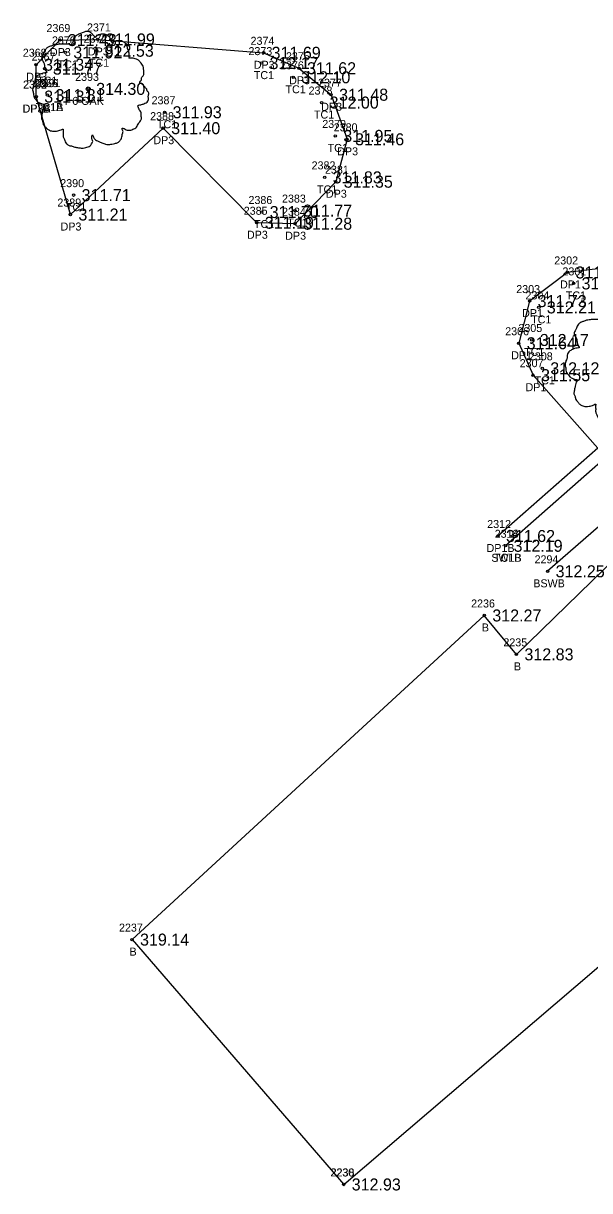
# Model space of a CAD drawing. Extents: x 1970076 to 1971136, y 803126 to 804215.
# Drawn here: x 1970276.2 to 1970347, y 803647.9 to 803793.8 of the extents above; entities that cross this region are included whole.
import ezdxf

# ---------------------------------------------------------------- set-up
doc = ezdxf.new("R2010")
doc.units = 0
for name, color, linetype in [('RD_EX_Bldg', 7, 'Continuous'), ('RD_EX_Bldg_txCode', 7, 'Continuous'), ('RD_EX_Conc', 7, 'Continuous'), ('RD_EX_Conc_txCode', 7, 'Continuous'), ('RD_EX_Driveway', 7, 'Continuous'), ('RD_EX_Driveway_txCode', 7, 'Continuous'), ('RD_EX_TX_Bldg_ELEV', 7, 'Continuous'), ('RD_EX_TX_Conc_ELEV', 7, 'Continuous'), ('RD_EX_TX_Driveway_ELEV', 7, 'Continuous'), ('RD_EX_TX_VEG_ELEV', 7, 'Continuous'), ('RD_EX_VEG', 7, 'Continuous'), ('RD_EX_VEG_txCode', 7, 'Continuous'), ('RD_SMD_Locator', 7, 'Continuous')]:
    doc.layers.add(name, color=color, linetype=linetype)

msp = doc.modelspace()

# ---------------------------------------------------------------- linework, layer by layer
at = {"layer": 'RD_EX_Bldg'}
msp.add_lwpolyline([(1970316.24, 803648.65), (1970363.89, 803689.38), (1970360.37, 803693.37), (1970387.33, 803715.2), (1970364.46, 803740.81), (1970337.82, 803714.9), (1970333.81, 803719.76), (1970289.79, 803679.25), (1970316.24, 803648.65)], dxfattribs=at)
at = {"layer": 'RD_EX_Conc'}
for points in [[(1970388.04, 803714.57), (1970387.81, 803720.9), (1970384.41, 803726.13), (1970362.2, 803751.39), (1970350.07, 803740.46), (1970336.46, 803728.47)], [(1970388.04, 803714.57), (1970384.87, 803718.14), (1970385.63, 803718.83), (1970368.14, 803738.61), (1970367.29, 803737.93), (1970364.41, 803741.02), (1970364.34, 803740.94), (1970361.22, 803738.42), (1970359.25, 803740.53), (1970341.72, 803725.28)]]:
    msp.add_lwpolyline(points, dxfattribs=at)
at = {"layer": 'RD_EX_Driveway'}
for points in [[(1970277.82, 803784.61), (1970277.79, 803788.59), (1970280.75, 803791.67), (1970285.5, 803791.75), (1970306.23, 803790.08), (1970310.65, 803788.15), (1970314.66, 803784.84), (1970316.66, 803779.27), (1970315.24, 803773.97), (1970310.16, 803768.72), (1970305.38, 803768.84), (1970293.68, 803780.66), (1970282.09, 803769.87), (1970277.82, 803784.61)], [(1970361.58, 803685.25), (1970385.16, 803706.07), (1970389.47, 803713.84), (1970389.3, 803721.4), (1970385.52, 803727.12), (1970356.23, 803760.4), (1970349.72, 803763.3), (1970344.21, 803762.63), (1970339.47, 803759.05), (1970338.11, 803753.78), (1970339.9, 803749.79), (1970347.99, 803740.68), (1970335.51, 803729.69)]]:
    msp.add_lwpolyline(points, dxfattribs=at)
at = {"layer": 'RD_EX_VEG'}
for centre, radius in [((1970284.31, 803785.57), 0.25), ((1970284.3, 803785.55), 0.0001)]:
    msp.add_circle(centre, radius, dxfattribs=at)
for points in [[(1970284.45, 803792.74), (1970284.15, 803792.76), (1970283.82, 803792.66), (1970283.57, 803792.56), (1970283.35, 803792.49), (1970283.12, 803792.39), (1970282.82, 803792.22), (1970282.6, 803792.02), (1970282.47, 803791.77), (1970282.42, 803791.54), (1970282.37, 803791.27), (1970282.37, 803791.09), (1970282.25, 803791.07), (1970282.1, 803791.09), (1970281.85, 803791.17), (1970281.6, 803791.17), (1970281.35, 803791.17), (1970281, 803791.14), (1970280.65, 803791.14), (1970280.37, 803791.09), (1970280.05, 803791.04), (1970279.67, 803790.92), (1970279.32, 803790.79), (1970279.02, 803790.54), (1970278.77, 803790.07), (1970278.65, 803789.72), (1970278.5, 803789.47), (1970278.65, 803789.02), (1970278.82, 803788.67), (1970278.85, 803788.47), (1970278.92, 803788.04), (1970279.02, 803787.82), (1970279.15, 803787.62), (1970279.07, 803787.59), (1970278.7, 803787.54), (1970278.4, 803787.44), (1970277.97, 803787.22), (1970277.75, 803786.99), (1970277.65, 803786.67), (1970277.62, 803786.32), (1970277.52, 803786.12), (1970277.45, 803785.84), (1970277.42, 803785.77), (1970277.37, 803785.44), (1970277.47, 803784.99), (1970277.5, 803784.64), (1970277.62, 803784.42), (1970277.77, 803784.24), (1970277.95, 803783.99), (1970278.35, 803783.77), (1970278.67, 803783.67), (1970278.87, 803783.64), (1970278.7, 803783.14), (1970278.65, 803782.79), (1970278.52, 803782.39), (1970278.52, 803782.32), (1970278.47, 803781.84), (1970278.62, 803781.52), (1970278.7, 803781.14), (1970278.87, 803780.92), (1970279.15, 803780.62), (1970279.47, 803780.4), (1970279.97, 803780.27), (1970280.37, 803780.3), (1970280.95, 803780.47), (1970281.2, 803780.55), (1970281.17, 803780.37), (1970281.2, 803780), (1970281.2, 803779.57), (1970281.35, 803779.25), (1970281.45, 803778.97), (1970281.6, 803778.72), (1970281.92, 803778.5), (1970282.32, 803778.42), (1970282.75, 803778.27), (1970283.2, 803778.2), (1970283.7, 803778.17), (1970284.3, 803778.32), (1970284.57, 803778.45), (1970284.67, 803778.62), (1970284.87, 803779), (1970284.82, 803779.22), (1970284.84, 803779.82), (1970284.94, 803779.65), (1970285.12, 803779.3), (1970285.62, 803779), (1970286.02, 803778.82), (1970286.49, 803778.67), (1970286.79, 803778.6), (1970287.27, 803778.67), (1970287.64, 803778.75), (1970288.02, 803778.87), (1970288.32, 803779.15), (1970288.49, 803779.42), (1970288.54, 803779.7), (1970288.62, 803780.07), (1970288.67, 803780.25)], [(1970288.67, 803780.25), (1970288.59, 803780.42), (1970288.54, 803780.67), (1970288.62, 803780.65), (1970288.79, 803780.6), (1970289.07, 803780.47), (1970289.29, 803780.4), (1970289.62, 803780.42), (1970289.89, 803780.52), (1970290.34, 803780.8), (1970290.62, 803781.27), (1970290.89, 803781.67), (1970290.97, 803781.99), (1970290.92, 803782.22), (1970290.89, 803782.72), (1970290.69, 803782.97), (1970290.64, 803783.09), (1970290.54, 803783.49), (1970290.62, 803783.54), (1970290.89, 803783.59), (1970291.27, 803783.72), (1970291.54, 803783.84), (1970291.77, 803784.02), (1970291.84, 803784.24), (1970291.82, 803784.64), (1970291.87, 803785.04), (1970291.79, 803785.19), (1970291.69, 803785.34), (1970291.62, 803785.54), (1970291.47, 803785.69), (1970291.37, 803785.84), (1970291.27, 803785.94), (1970291.14, 803786.09), (1970290.97, 803786.22), (1970290.82, 803786.27), (1970290.77, 803786.42), (1970290.92, 803786.62), (1970290.97, 803786.72), (1970290.99, 803786.94), (1970291.22, 803787.29), (1970291.27, 803787.69), (1970291.22, 803788.12), (1970291.17, 803788.39), (1970291.02, 803788.67), (1970290.82, 803788.92), (1970290.69, 803789.09), (1970290.52, 803789.22), (1970290.19, 803789.34), (1970289.94, 803789.39), (1970289.59, 803789.39), (1970289.39, 803789.44), (1970289.42, 803789.49), (1970289.42, 803789.64), (1970289.42, 803789.92), (1970289.34, 803790.37), (1970289.19, 803790.87), (1970289.19, 803790.89), (1970289.09, 803791.14), (1970288.87, 803791.34), (1970288.69, 803791.44), (1970288.49, 803791.57), (1970288.24, 803791.59), (1970287.94, 803791.59), (1970287.67, 803791.54), (1970287.47, 803791.44), (1970287.29, 803791.32), (1970287.22, 803791.47), (1970287.12, 803791.77), (1970287.07, 803791.92), (1970286.92, 803792.09), (1970286.69, 803792.29), (1970286.24, 803792.41), (1970285.62, 803792.34), (1970285.32, 803792.14), (1970285.17, 803791.97), (1970285.12, 803792.09), (1970284.92, 803792.29), (1970284.82, 803792.46), (1970284.64, 803792.59), (1970284.5, 803792.69), (1970284.4, 803792.74)], [(1970350.98, 803758.35), (1970350.68, 803758.37), (1970350.35, 803758.27), (1970350.1, 803758.17), (1970349.88, 803758.1), (1970349.65, 803758), (1970349.35, 803757.82), (1970349.13, 803757.62), (1970349, 803757.37), (1970348.95, 803757.15), (1970348.9, 803756.87), (1970348.9, 803756.7), (1970348.78, 803756.67), (1970348.63, 803756.7), (1970348.38, 803756.77), (1970348.13, 803756.77), (1970347.88, 803756.77), (1970347.53, 803756.75), (1970347.18, 803756.75), (1970346.9, 803756.7), (1970346.58, 803756.65), (1970346.21, 803756.52), (1970345.86, 803756.4), (1970345.56, 803756.15), (1970345.31, 803755.67), (1970345.18, 803755.32), (1970345.03, 803755.07), (1970345.18, 803754.62), (1970345.36, 803754.27), (1970345.38, 803754.07), (1970345.46, 803753.65), (1970345.56, 803753.42), (1970345.68, 803753.22), (1970345.61, 803753.2), (1970345.23, 803753.15), (1970344.93, 803753.05), (1970344.51, 803752.82), (1970344.28, 803752.6), (1970344.18, 803752.27), (1970344.16, 803751.92), (1970344.06, 803751.72), (1970343.98, 803751.45), (1970343.96, 803751.37), (1970343.91, 803751.05), (1970344.01, 803750.6), (1970344.03, 803750.25), (1970344.16, 803750.02), (1970344.31, 803749.85), (1970344.48, 803749.6), (1970344.88, 803749.37), (1970345.21, 803749.27), (1970345.41, 803749.25), (1970345.23, 803748.75), (1970345.18, 803748.4), (1970345.06, 803748), (1970345.06, 803747.93), (1970345.01, 803747.45), (1970345.16, 803747.13), (1970345.23, 803746.75), (1970345.41, 803746.53), (1970345.68, 803746.23), (1970346.01, 803746), (1970346.51, 803745.88), (1970346.9, 803745.9), (1970347.48, 803746.08), (1970347.73, 803746.15), (1970347.7, 803745.98), (1970347.73, 803745.6), (1970347.73, 803745.18), (1970347.88, 803744.85), (1970347.98, 803744.58), (1970348.13, 803744.33), (1970348.45, 803744.1), (1970348.85, 803744.03), (1970349.28, 803743.88), (1970349.73, 803743.8), (1970350.23, 803743.78), (1970350.83, 803743.93), (1970351.1, 803744.05), (1970351.2, 803744.23), (1970351.4, 803744.6), (1970351.35, 803744.83), (1970351.38, 803745.43), (1970351.48, 803745.25), (1970351.65, 803744.9), (1970352.15, 803744.6), (1970352.55, 803744.43), (1970353.03, 803744.28), (1970353.33, 803744.2), (1970353.8, 803744.28), (1970354.18, 803744.35), (1970354.55, 803744.48), (1970354.85, 803744.75), (1970355.03, 803745.03), (1970355.08, 803745.3), (1970355.15, 803745.68), (1970355.2, 803745.85)]]:
    msp.add_spline(points, degree=3, dxfattribs=at)
at = {"layer": 'RD_SMD_Locator'}
for centre in [(1970280.75, 803791.67), (1970285.5, 803791.75), (1970281.45, 803790.13), (1970285.37, 803790.34), (1970306.23, 803790.08), (1970277.79, 803788.59), (1970278.89, 803788.1), (1970305.97, 803788.79), (1970310.65, 803788.15), (1970309.93, 803787.02), (1970277.82, 803784.61), (1970277.82, 803784.61), (1970279.22, 803784.79), (1970279.22, 803784.79), (1970284.31, 803785.57), (1970314.66, 803784.84), (1970313.48, 803783.86), (1970293.86, 803782.65), (1970293.68, 803780.66), (1970315.19, 803779.69), (1970316.66, 803779.27), (1970313.86, 803774.51), (1970315.24, 803773.97), (1970282.49, 803772.29), (1970305.99, 803770.18), (1970310.16, 803770.36), (1970282.09, 803769.87), (1970305.38, 803768.84), (1970310.16, 803768.72), (1970344.21, 803762.63), (1970344.96, 803761.26), (1970339.47, 803759.05), (1970340.62, 803758.26), (1970339.74, 803754.19), (1970338.11, 803753.78), (1970339.9, 803749.79), (1970341.05, 803750.65), (1970335.51, 803729.69), (1970336.46, 803728.47), (1970336.46, 803728.47), (1970341.72, 803725.28), (1970333.81, 803719.76), (1970337.82, 803714.9), (1970289.79, 803679.25), (1970316.24, 803648.65), (1970316.24, 803648.65)]:
    msp.add_circle(centre, 0.15, dxfattribs=at)

# ---------------------------------------------------------------- texts
at = {"layer": 'RD_EX_Bldg_txCode'}
for s, p in [('2236', (1970332.16, 803720.76)), ('B', (1970333.5, 803717.76)), ('2235', (1970336.19, 803715.9)), ('B', (1970337.51, 803712.9)), ('2237', (1970288.16, 803680.25)), ('B', (1970289.48, 803677.25)), ('2230', (1970314.57, 803649.65)), ('2238', (1970314.61, 803649.65))]:
    msp.add_text(s, height=1, dxfattribs=at).set_placement(p)
at = {"layer": 'RD_EX_Conc_txCode'}
for s, p in [('2370', (1970279.78, 803791.13)), ('2372', (1970283.74, 803791.34)), ('2373', (1970304.34, 803789.79)), ('2367', (1970277.24, 803789.1)), ('TC1', (1970280.49, 803788.13)), ('TC1', (1970284.4, 803788.34)), ('TC1', (1970305.01, 803786.79)), ('2376', (1970308.28, 803788.02)), ('2366', (1970277.54, 803785.79)), ('2391', (1970277.87, 803785.79)), ('TC1', (1970277.93, 803786.1)), ('TC1', (1970308.97, 803785.02)), ('2378', (1970311.85, 803784.86)), ('TC1A', (1970277.77, 803782.79)), ('TC1B', (1970277.79, 803782.79)), ('2387', (1970292.23, 803783.65)), ('TC1', (1970312.52, 803781.86)), ('TC1', (1970292.9, 803780.65)), ('2379', (1970313.56, 803780.69)), ('TC1', (1970314.23, 803777.69)), ('2382', (1970312.23, 803775.51)), ('2390', (1970280.82, 803773.29)), ('TC1', (1970312.9, 803772.51)), ('2386', (1970304.34, 803771.18)), ('2383', (1970308.53, 803771.36)), ('TC1', (1970281.53, 803770.29)), ('TC1', (1970305.03, 803768.18)), ('TC1', (1970309.2, 803768.36)), ('2301', (1970343.57, 803762.26)), ('2304', (1970338.95, 803759.26)), ('TC1', (1970344, 803759.26)), ('TC1', (1970339.66, 803756.26)), ('2305', (1970338.07, 803755.19)), ('TC1', (1970338.78, 803752.19)), ('2308', (1970339.38, 803751.65)), ('TC1', (1970340.09, 803748.65)), ('2313', (1970335.11, 803729.47)), ('2314', (1970335.11, 803729.47)), ('SWLB', (1970334.69, 803726.47)), ('TC1B', (1970335.02, 803726.47)), ('2294', (1970340.09, 803726.28)), ('BSWB', (1970339.93, 803723.28))]:
    msp.add_text(s, height=1, dxfattribs=at).set_placement(p)
at = {"layer": 'RD_EX_Driveway_txCode'}
for s, p in [('2369', (1970279.1, 803792.67)), ('2371', (1970284.16, 803792.75)), ('2374', (1970304.6, 803791.08)), ('2368', (1970276.14, 803789.59)), ('DP3', (1970279.53, 803789.67)), ('DP3', (1970284.28, 803789.75)), ('DP3', (1970305, 803788.08)), ('2375', (1970309.02, 803789.15)), ('2365', (1970276.17, 803785.61)), ('2392', (1970276.19, 803785.61)), ('DP3', (1970276.57, 803786.59)), ('DP3', (1970309.42, 803786.15)), ('2377', (1970313.03, 803785.84)), ('DP3A', (1970276.1, 803782.61)), ('DP3B', (1970276.12, 803782.61)), ('DP3', (1970313.43, 803782.84)), ('2388', (1970292.05, 803781.66)), ('2380', (1970314.99, 803780.27)), ('DP3', (1970292.45, 803778.66)), ('DP3', (1970315.43, 803777.27)), ('2381', (1970313.9, 803774.97)), ('2389', (1970280.46, 803770.87)), ('DP3', (1970314.02, 803771.97)), ('2385', (1970303.75, 803769.84)), ('2384', (1970308.53, 803769.72)), ('DP3', (1970280.86, 803767.87)), ('DP3', (1970304.15, 803766.84)), ('DP3', (1970308.93, 803766.72)), ('2302', (1970342.55, 803763.63)), ('DP1', (1970343.27, 803760.63)), ('2303', (1970337.8, 803760.05)), ('DP1', (1970338.53, 803757.05)), ('2306', (1970336.42, 803754.78)), ('DP1', (1970337.17, 803751.78)), ('2307', (1970338.23, 803750.79)), ('DP1', (1970338.96, 803747.79)), ('2312', (1970334.17, 803730.69)), ('DP1B', (1970334.09, 803727.69))]:
    msp.add_text(s, height=1, dxfattribs=at).set_placement(p)
at = {"layer": 'RD_EX_TX_Bldg_ELEV'}
for s, p in [('312.27', (1970334.81, 803719.01)), ('312.83', (1970338.82, 803714.15)), ('319.14', (1970290.79, 803678.5)), ('312.93', (1970317.24, 803647.9)), ('312.93', (1970317.24, 803647.9))]:
    msp.add_text(s, height=1.5, dxfattribs=at).set_placement(p)
at = {"layer": 'RD_EX_TX_Conc_ELEV'}
for s, p in [('311.92', (1970282.45, 803789.38)), ('312.53', (1970286.37, 803789.59)), ('312.17', (1970306.97, 803788.04)), ('311.77', (1970279.89, 803787.35)), ('312.10', (1970310.93, 803786.27)), ('311.81', (1970280.22, 803784.04)), ('311.81', (1970280.22, 803784.04)), ('311.93', (1970294.86, 803781.9)), ('312.00', (1970314.48, 803783.11)), ('311.95', (1970316.19, 803778.94)), ('311.83', (1970314.86, 803773.76)), ('311.71', (1970283.49, 803771.54)), ('311.70', (1970306.99, 803769.43)), ('311.77', (1970311.16, 803769.61)), ('312.28', (1970345.96, 803760.51)), ('312.21', (1970341.62, 803757.51)), ('312.17', (1970340.74, 803753.44)), ('312.12', (1970342.05, 803749.9)), ('312.19', (1970337.46, 803727.72)), ('312.19', (1970337.46, 803727.72)), ('312.25', (1970342.72, 803724.53))]:
    msp.add_text(s, height=1.5, dxfattribs=at).set_placement(p)
at = {"layer": 'RD_EX_TX_Driveway_ELEV'}
for s, p in [('311.43', (1970281.75, 803790.92)), ('311.99', (1970286.5, 803791)), ('311.69', (1970307.23, 803789.33)), ('311.34', (1970278.79, 803787.84)), ('311.62', (1970311.65, 803787.4)), ('311.31', (1970278.82, 803783.86)), ('311.31', (1970278.82, 803783.86)), ('311.48', (1970315.66, 803784.09)), ('311.40', (1970294.68, 803779.91)), ('311.46', (1970317.66, 803778.52)), ('311.35', (1970316.24, 803773.22)), ('311.21', (1970283.09, 803769.12)), ('311.19', (1970306.38, 803768.09)), ('311.28', (1970311.16, 803767.97)), ('311.77', (1970345.21, 803761.88)), ('311.73', (1970340.47, 803758.3)), ('311.64', (1970339.11, 803753.03)), ('311.55', (1970340.9, 803749.04)), ('311.62', (1970336.51, 803728.94))]:
    msp.add_text(s, height=1.5, dxfattribs=at).set_placement(p)
at = {"layer": 'RD_EX_TX_VEG_ELEV'}
msp.add_text('314.30', height=1.5, dxfattribs=at).set_placement((1970285.31, 803784.82))
at = {"layer": 'RD_EX_VEG_txCode'}
for s, p in [('2393', (1970282.68, 803786.57)), ('T 6 OAK', (1970281.13, 803783.57))]:
    msp.add_text(s, height=1, dxfattribs=at).set_placement(p)

doc.saveas('drawing.dxf')
